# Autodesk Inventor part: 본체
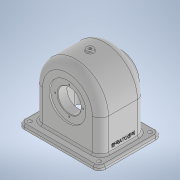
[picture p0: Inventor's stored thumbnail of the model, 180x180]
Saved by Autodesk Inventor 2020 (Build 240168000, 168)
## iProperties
Created: 2022-09
Part Number: 본체
Material: 일반
Document SubType Name: Modeling
Designer: Administrator
Density: 1 g/cm^3
Appearance: 기본값
Mass: 290.754 g
Surface Area: 1042.06 cm^2
Volume: 290.754 cm^3
Author: Administrator
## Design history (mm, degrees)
sketch "스케치1"
  geometry: L1 (-70, 54)-(70, 54); L2 (70, 54)-(70, -54); L3 (70, -54)-(-70, -54); L4 (-70, -54)-(-70, 54); L5 (-70, 54)-(70, -54); L6 (70, 54)-(-70, -54); 1 further point
  constraints: 12 end point, 2 midpoint, 2 parallel, 1 horizontal, 1 perpendicular
  dimensions: "d0" = 140 distance of L1.start L1.end; "d1" = 108 distance of L3.end L1.start
extrude "돌출1" new body sketch "스케치1" distance "d2" = 7; taper "d3" = 0 deg
fillet "모깎기1" dims "d4" = 10
sketch "스케치2"
  geometry: A1 r 10 centre (60, -44) between (60, -54) and (70, -44) reference; 2 further points
  constraints: 1 coincident
hole "구멍1" sketch "스케치2" at (60, -44) diameter "d5" = 6.6; stored, may be unused: countersink angle "d9" = 90 deg, drill point angle "d11" = 118 deg; dims "d6" = 11, "d7" = 4, "d8" = 2, "d10" = 13
sketch "스케치3"
  geometry: L1 (57, 64)-(57, 7); L2 (60, 7)-(70, 7) reference; L3 (-57, 64)-(-57, 7); L4 (-60, 0)-(60, 0) reference; L5 (57, 7)-(-57, 7); L6 (-56.7, 0)-(-56.7, 7) reference; A1 r 57 centre (0, 64) between (57, 64) and (-57, 64); 1 further point
  constraints: 6 end point, 2 point on circle, 2 tangent, 2 vertical, 1 centre point, 1 perpendicular, 1 point on line, 1 vertical alignment
  dimensions: "d16" = 114 diameter of A1; "d17" = 64 distance from line of L4 A1.centre
extrude "돌출2" new body sketch "스케치3" stored distance "d18" = 78; taper "d19" = 0 deg
fillet "모깎기2" dims "d20" = 14
feature "쉘1" dims "d21" = 5
sketch "스케치4"
  geometry: L1 (-52, -25)-(-52, 25) reference; L2 (-43, 34)-(43, 34) reference; L3 (52, 25)-(52, -25) reference; L4 (43, -34)-(-43, -34) reference; A1 r 9 centre (-43, 25) between (-43, 34) and (-52, 25) reference; A2 r 9 centre (43, 25) between (52, 25) and (43, 34) reference; A3 r 9 centre (43, -25) between (43, -34) and (52, -25) reference; A4 r 9 centre (-43, -25) between (-52, -25) and (-43, -34) reference; 1 further point
extrude "돌출3" cut sketch "스케치4" distance "d22" = 10; taper "d23" = 0 deg
feature "결합1"
  node "솔리드1"
sketch "스케치5"
  geometry: L1 (-39, 7)-(-39, 64) reference; L2 (-39, 64)-(67.883, 64); L3 (-20, 92)-(-20, 64); L4 (-25, 64)-(25, 64) reference; L5 (-20, 92)-(-34, 100.083); L6 (-34, 64)-(-34, 107) reference; L7 (-34, 0)-(-34, 64) reference; L8 (-34, 100.083)-(-34, 64); 2 further points
  constraints: 8 end point, 2 point on line, 1 horizontal, 1 perpendicular, 1 vertical
  dimensions: "d24" = 56 diameter of L3.start L2; "d25" = 60 deg angle of L3 L5; "d26" = 14 distance between parallel lines of L6 L3
revolve "회전1" sketch "스케치5" stored, may be unused: angle "d27" = 90 deg
sketch "스케치6"
  geometry: A1 r 43 centre (0, 64) between (43, 64) and (-43, 64) reference; 2 further points
  constraints: 1 coincident
hole "구멍2" sketch "스케치6" at (0, 64) diameter "d28" = 40; stored, may be unused: countersink angle "d32" = 90 deg, drill point angle "d34" = 0 deg; dims "d29" = 11, "d30" = 64, "d31" = 3, "d33" = 13
node "작업 평면1"
sketch "스케치7"
  geometry: C1 r 31 at (0, -64); A1 r 43 centre (0, -64) between (-43, -64) and (43, -64) reference; 1 further point
  constraints: 1 centre point, 1 coincident
  dimensions: "d36" = 62 diameter of C1
extrude "돌출4" join sketch "스케치7" stored distance "d37" = 10; taper "d38" = 0 deg
sketch "스케치8"
  geometry: C1 r 31 at (0, 0) reference; 2 further points
  constraints: 1 coincident
hole "구멍3" sketch "스케치8" at (0, 0) diameter "d39" = 35; stored, may be unused: countersink angle "d43" = 90 deg, drill point angle "d45" = 0 deg; dims "d40" = 11, "d41" = 40, "d42" = 16, "d44" = 13
node "작업 평면2"
sketch "스케치9"
  geometry: C1 r 6 at (-60, -54); 1 further point
  constraints: 1 centre point, 1 coincident
  dimensions: "d47" = 12 diameter of C1
extrude "돌출5" join sketch "스케치9" stored distance "d48" = 10; taper "d49" = 0 deg
sketch "스케치10"
  geometry: C1 r 6 at (0, 0) reference; 2 further points
  constraints: 1 coincident
hole "구멍4" sketch "스케치10" at (0, 0) diameter "d50" = 5.1881; stored, may be unused: countersink angle "d54" = 90 deg, drill point angle "d56" = 0 deg; dims "d51" = 12, "d52" = 40, "d53" = 16, "d55" = 16
fillet "모깎기3" dims "d57" = 1
sketch "스케치11"
  geometry: C1 r 32 at (0, 0) reference; 2 further points
  constraints: 1 vertical alignment
  dimensions: "d58" = 24 distance of C1.centre point (0, 24)
hole "구멍5" sketch "스케치11" at (0, 24) diameter "d59" = 2.459; stored, may be unused: countersink angle "d63" = 90 deg, drill point angle "d65" = 118 deg; dims "d60" = 7, "d61" = 40, "d62" = 16, "d64" = 9
sketch "스케치12"
  geometry: C1 r 20 at (0, 0) reference; 2 further points
  constraints: 1 vertical alignment
  dimensions: "d69" = 24 distance of C1.centre point (0, -24)
hole "구멍6" sketch "스케치12" at (0, -24) diameter "d70" = 2.459; stored, may be unused: countersink angle "d74" = 90 deg, drill point angle "d76" = 118 deg; dims "d71" = 7, "d72" = 40, "d73" = 16, "d75" = 9
node "작업 평면3"
sketch "스케치13"
  geometry: L1 (64, -19)-(64, -29) reference; L2 (0, -14)-(57, -14) reference; 2 further points
  constraints: 1 other
  dimensions: "d81" = 17 distance from line of point (47, 25) L1; "d82" = 39 distance from line of point (47, 25) L2
feature "엠보싱1" sketch "스케치13" dims "d0" = 140, "d1" = 108, "d83" = 0.5, "d84" = 0
fillet "모깎기4" dims "d85" = 0.6
chamfer "모따기1" distance "d86" = 1; stored, may be unused: second distance "d87" = 2, angle "d88" = 45 deg
fillet "모깎기5" dims "d89" = 3
pattern_linear "직사각형 패턴1"
pattern_circular "원형 패턴1" dims angle "d67" = 360 deg
pattern_circular "원형 패턴2" dims angle "d78" = 360 deg
node "솔리드2"
feature "A9D066F2-1C7D-4E18-AEED-F7BC21143FA4" dims "d5" = 6.6, "d6" = 11, "d7" = 4, "d8" = 2, "d9" = 90 deg, "d10" = 13, "d11" = 118 deg
other parameters: "d35" = 15, "d46" = -124
